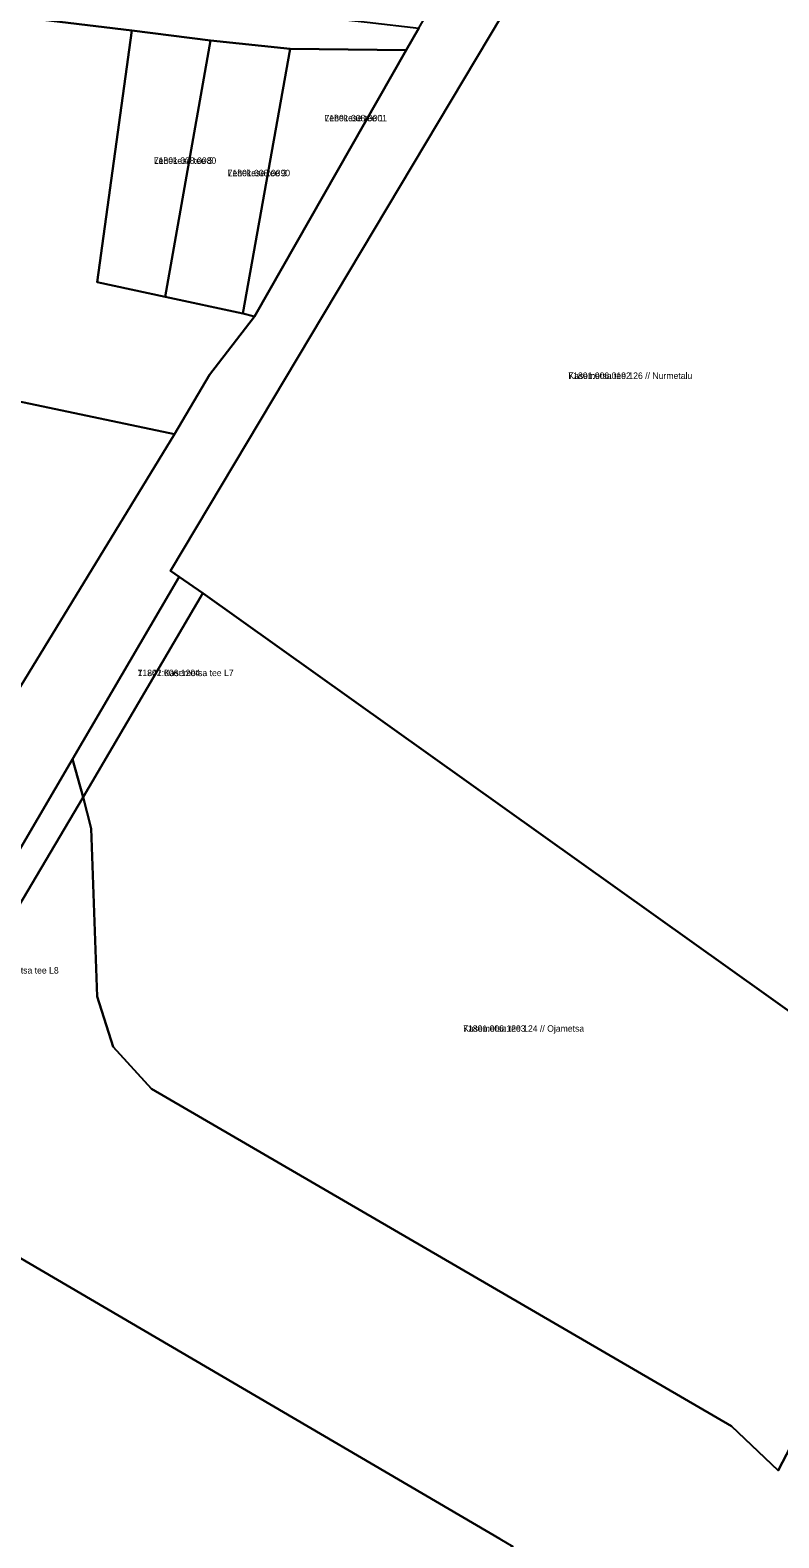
# Model space of a CAD drawing. Extents: x 529768 to 552006, y 6562269 to 6580975.
# Drawn here: x 537612.3 to 537786.2, y 6569289.3 to 6569639.3 of the extents above; entities that cross this region are included whole.
import ezdxf

# ---------------------------------------------------------------- set-up
doc = ezdxf.new("R2010")
doc.units = 0
for name, color, linetype in [('L_AADRESS', 7, 'Continuous'), ('PIIR', 7, 'Continuous'), ('TUNNUS', 7, 'Continuous')]:
    doc.layers.add(name, color=color, linetype=linetype)

msp = doc.modelspace()

# ---------------------------------------------------------------- linework, layer by layer
at = {"layer": 'PIIR'}
for points in [[(537281.43, 6569019.46), (537368.89, 6569121.58), (537420.6, 6569181.09), (537438.26, 6569204.93), (537445.15, 6569209.46), (537456.97, 6569225.74), (537523.87, 6569335.93), (537530.38, 6569351.64), (537552.48, 6569389.3), (537556.5, 6569395.83), (537567.78, 6569415.59), (537578.32, 6569433.84), (537588.9, 6569451.99), (537598.21, 6569467.74), (537645.8, 6569545.54), (537653.92, 6569559.3), (537664.42, 6569572.88), (537699.62, 6569634.71), (537702.59, 6569639.82), (537731.22, 6569689.57), (537747.58, 6569702.72), (538032.41, 6569935.34), (538189.88, 6570063.68)], [(537745.56, 6569682.43), (537644.87, 6569513.8), (537646.93, 6569512.39), (537622.11, 6569470.11), (537568.68, 6569378.74)], [(537513.09, 6569573.49), (537645.8, 6569545.54), (537598.21, 6569467.74)], [(537721.35, 6569289.12), (537573.72, 6569375.48), (537624.58, 6569461.25), (537626.51, 6569454), (537627.83, 6569414.98), (537631.6, 6569403.29), (537640.51, 6569393.56), (537775.21, 6569315.27), (537785.99, 6569305), (537827.2, 6569384.07), (537829.72, 6569390.65), (537875.39, 6569364.34), (537887.64, 6569351.98), (537910.34, 6569323.52), (537930.2, 6569314.79), (537955.26, 6569303.77), (537967.26, 6569298.54), (537937.3, 6569295.77), (537933.41, 6569293.13), (537934.56, 6569291.38), (538063.49, 6569111.53)]]:
    msp.add_lwpolyline(points, dxfattribs=at)
for points in [[(537635.95, 6569639.23), (537547.78, 6569649.91), (537546.01, 6569710.64), (537587.98, 6569705.34), (537582.4, 6569654.98), (537601.05, 6569652.57), (537619.24, 6569650.03), (537637.33, 6569647.48), (537655.29, 6569645.19), (537672.82, 6569643.09), (537690.57, 6569641.16), (537702.59, 6569639.82), (537699.62, 6569634.71), (537672.69, 6569634.96), (537654.17, 6569636.94)], [(537644.87, 6569513.8), (537745.56, 6569682.43), (537776.26, 6569709.01), (537777.15, 6569706.14), (537791.22, 6569661.26), (537799.74, 6569628.48), (537806.35, 6569603.16), (537817.69, 6569559.7), (537816.3, 6569541.46), (537814.78, 6569521.51), (537813.21, 6569500.95), (537811.25, 6569475.13), (537808.72, 6569441.91), (537816.76, 6569422.27), (537825.47, 6569401.03), (537829.72, 6569390.65), (537827.2, 6569384.07), (537652.4, 6569508.66), (537646.93, 6569512.39)], [(537547.78, 6569649.91), (537635.95, 6569639.23), (537627.87, 6569580.82), (537643.65, 6569577.43), (537661.73, 6569573.54), (537664.42, 6569572.88), (537653.92, 6569559.3), (537645.8, 6569545.54), (537513.09, 6569573.49), (537510.21, 6569574.1), (537540.15, 6569625.74), (537542.63, 6569633.45), (537542.21, 6569650.49)], [(537635.95, 6569639.23), (537654.17, 6569636.94), (537643.65, 6569577.43), (537627.87, 6569580.82)], [(537654.17, 6569636.94), (537672.69, 6569634.96), (537661.73, 6569573.54), (537643.65, 6569577.43)], [(537672.69, 6569634.96), (537699.62, 6569634.71), (537664.42, 6569572.88), (537661.73, 6569573.54)], [(537646.93, 6569512.39), (537652.4, 6569508.66), (537624.58, 6569461.25), (537622.11, 6569470.11)], [(537624.58, 6569461.25), (537652.4, 6569508.66), (537827.2, 6569384.07), (537785.99, 6569305), (537775.21, 6569315.27), (537640.51, 6569393.56), (537631.6, 6569403.29), (537627.83, 6569414.98), (537626.51, 6569454)], [(537622.11, 6569470.11), (537624.58, 6569461.25), (537573.72, 6569375.48), (537568.68, 6569378.74)], [(537573.72, 6569375.48), (537721.35, 6569289.12), (537724.42, 6569287.32), (537584.93, 6569195.2), (537580.98, 6569196.31), (537483.59, 6569223.61), (537532.46, 6569305.9), (537550.3, 6569330.48), (537557.07, 6569345.82)]]:
    msp.add_lwpolyline(points, close=True, dxfattribs=at)

# ---------------------------------------------------------------- texts
at = {"layer": 'L_AADRESS'}
for s, p in [('Lehekese tee 1', (537680.67, 6569618.16)), ('Lehekese tee 5', (537641.02, 6569608.29)), ('Lehekese tee 3', (537658.17, 6569605.41)), ('Kasemetsa tee 126 // Nurmetalu', (537737.29, 6569558.37)), ('11242 Kasemetsa tee L7', (537637.25, 6569489.38)), ('11242 Kasemetsa tee L8', (537596.63, 6569420.33)), ('Kasemetsa tee 124 // Ojametsa', (537712.86, 6569406.83))]:
    msp.add_text(s, height=1.5, dxfattribs=at).set_placement(p)
at = {"layer": 'TUNNUS'}
for s, p in [('71801:008:0001', (537680.67, 6569618.16)), ('71801:008:0080', (537641.02, 6569608.29)), ('71801:008:0090', (537658.17, 6569605.41)), ('71801:006:0192', (537737.29, 6569558.37)), ('71801:006:1204', (537637.25, 6569489.38)), ('71801:006:1203', (537712.86, 6569406.83))]:
    msp.add_text(s, height=1.5, dxfattribs=at).set_placement(p)

doc.saveas('drawing.dxf')
